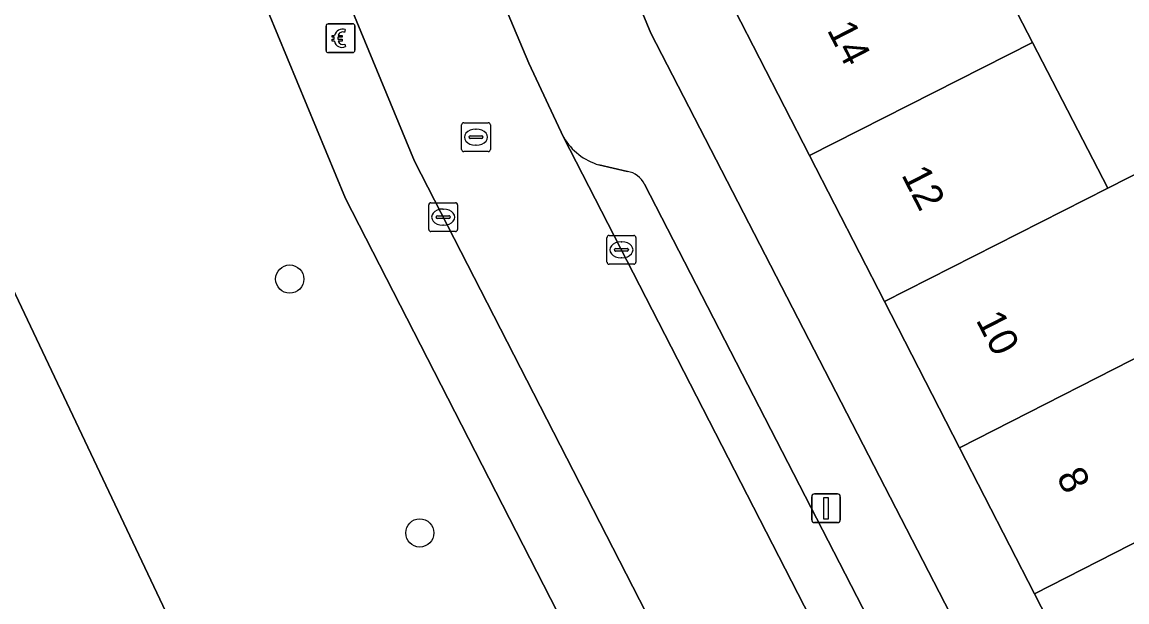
# Model space of a CAD drawing. Extents: x 160377 to 161131, y 383938 to 384853.
# Drawn here: x 161013.12 to 161051.44, y 384168.41 to 384188.53 of the extents above; entities that cross this region are included whole.
import ezdxf

# ---------------------------------------------------------------- set-up
doc = ezdxf.new("R2010")
doc.units = 0
for name, color, linetype in [('IMGEO_Betaalautomaat', 7, 'Continuous'), ('IMGEO_Boom', 7, 'Continuous'), ('IMGEO_Erf', 7, 'Continuous'), ('IMGEO_Groenvoorziening', 7, 'Continuous'), ('IMGEO_Kolk', 7, 'Continuous'), ('IMGEO_Lichtmast', 7, 'Continuous'), ('IMGEO_Pand', 7, 'Continuous'), ('IMGEO_Pand_nummerreeks', 7, 'Continuous'), ('IMGEO_Parkeervlak_open', 7, 'Continuous'), ('IMGEO_Rijbaan_lokaal_open', 7, 'Continuous'), ('IMGEO_Rioolput', 7, 'Continuous'), ('IMGEO_Voetpad_open', 7, 'Continuous')]:
    doc.layers.add(name, color=color, linetype=linetype)

msp = doc.modelspace()

# ---------------------------------------------------------------- linework, layer by layer
at = {"layer": 'IMGEO_Betaalautomaat'}
for p, q in [((161023.661, 384187.549), (161023.661, 384188.39)), ((161023.661, 384188.39), (161023.661, 384187.549)), ((161023.736, 384188.473), (161024.577, 384188.473)), ((161024.577, 384188.473), (161023.736, 384188.473)), ((161024.66, 384188.399), (161024.66, 384187.558)), ((161024.66, 384187.558), (161024.66, 384188.399)), ((161023.944, 384187.937), (161023.944, 384188.005)), ((161024.065, 384188.005), (161024.065, 384187.937)), ((161024.323, 384188.278), (161024.306, 384188.178)), ((161024.31, 384187.772), (161024.332, 384187.685)), ((161024.586, 384187.474), (161023.745, 384187.474)), ((161023.745, 384187.474), (161024.586, 384187.474))]:
    msp.add_line(p, q, dxfattribs=at)
for points in [[(161023.944, 384188.005), (161023.875, 384188.005), (161023.875, 384188.074), (161023.954, 384188.074)], [(161024.076, 384188.074), (161024.223, 384188.074), (161024.223, 384188.005), (161024.065, 384188.005)], [(161023.949, 384187.868), (161023.875, 384187.868), (161023.875, 384187.937), (161023.944, 384187.937)], [(161024.065, 384187.937), (161024.223, 384187.937), (161024.223, 384187.868), (161024.079, 384187.868)]]:
    msp.add_lwpolyline(points, dxfattribs=at)
for centre, radius, start, end in [((161023.739, 384188.396), 0.0779, 92.4484, 184.2845), ((161023.739, 384188.396), 0.0779, 92.4484, 184.2845), ((161024.583, 384188.396), 0.0779, 2.4484, 94.2845), ((161024.583, 384188.396), 0.0779, 2.4484, 94.2845), ((161024.237, 384187.998), 0.293, 73.014, 165.0139), ((161024.243, 384188.011), 0.179, 69.3236, 159.5683), ((161024.21, 384187.923), 0.267, 191.8096, 297.0389), ((161024.243, 384187.938), 0.179, 202.7625, 291.8693), ((161023.739, 384187.552), 0.0779, 182.4484, 274.2845), ((161023.739, 384187.552), 0.0779, 182.4484, 274.2845), ((161024.583, 384187.552), 0.0779, 272.4484, 4.2845), ((161024.583, 384187.552), 0.0779, 272.4484, 4.2845)]:
    msp.add_arc(centre, radius, start, end, dxfattribs=at)
at = {"layer": 'IMGEO_Boom'}
for centre in [(161022.4, 384179.616), (161026.913, 384170.805)]:
    msp.add_circle(centre, 0.489, dxfattribs=at)
at = {"layer": 'IMGEO_Erf'}
for points in [[(161027.847, 384235.775), (161032.783, 384223.835), (161034.958, 384218.572), (161037.135, 384213.306), (161039.745, 384214.388), (161041.92, 384209.128), (161044.101, 384203.852), (161046.188, 384198.804), (161043.598, 384197.672), (161045.71, 384192.581), (161048.165, 384187.827), (161050.776, 384182.773), (161053.527, 384184.17)], [(161050.73, 384163.819), (161048.231, 384168.689), (161045.627, 384173.765), (161043.025, 384178.835), (161040.426, 384183.902), (161037.824, 384188.973), (161035.658, 384194.201), (161033.482, 384199.465), (161031.304, 384204.732), (161029.129, 384209.995), (161026.959, 384215.243), (161024.801, 384220.463), (161022.879, 384219.642), (161021.24, 384223.614), (161020.418, 384223.235), (161034.926, 384188.154), (161057.391, 384144.576)]]:
    msp.add_lwpolyline(points, dxfattribs=at)
at = {"layer": 'IMGEO_Groenvoorziening'}
for points in [[(161024.34, 384182.407), (161021.323, 384189.711), (161011.935, 384212.434), (161011.739, 384212.907), (161011.64, 384213.064), (161011.528, 384213.211), (161011.402, 384213.348), (161011.265, 384213.472), (161011.118, 384213.585), (161010.961, 384213.683), (161010.796, 384213.767), (161010.624, 384213.836), (161010.446, 384213.889), (161010.265, 384213.927), (161010.081, 384213.948), (161009.895, 384213.952), (161009.71, 384213.94), (161009.527, 384213.911), (161009.347, 384213.866), (161009.172, 384213.806), (161009.003, 384213.729), (161008.989, 384213.722), (161000, 384208.958), (160981.618, 384199.217)], [(160990.804, 384145.659), (160994.784, 384139.197), (160994.905, 384139.173), (160998.463, 384138.478), (161007.166, 384134.542), (161007.773, 384134.636), (161029.797, 384138.079), (161029.845, 384138.087), (161029.42, 384139.864), (161026.658, 384162.899), (161031.19, 384164.897), (161032.918, 384165.659), (161032.625, 384166.23), (161024.34, 384182.407)]]:
    msp.add_lwpolyline(points, dxfattribs=at)
for points in [[(160994.141, 384181.268), (161013.455, 384140.491), (161027.915, 384147.34), (161008.602, 384188.117)], [(160994.141, 384181.268), (161008.602, 384188.117), (161027.915, 384147.34), (161013.455, 384140.491)]]:
    msp.add_lwpolyline(points, close=True, dxfattribs=at)
at = {"layer": 'IMGEO_Kolk'}
for p, q in [((161027.298, 384182.266), (161028.15, 384182.266)), ((161027.223, 384181.34), (161027.223, 384182.192)), ((161027.711, 384182.046), (161027.736, 384182.046)), ((161028.224, 384182.192), (161028.224, 384181.34)), ((161027.482, 384181.76), (161027.482, 384181.772)), ((161027.92, 384181.723), (161027.522, 384181.723)), ((161027.525, 384181.809), (161027.923, 384181.809)), ((161027.734, 384181.486), (161027.709, 384181.486)), ((161027.966, 384181.772), (161027.966, 384181.76)), ((161028.15, 384181.266), (161027.298, 384181.266)), ((161033.48, 384181.131), (161034.332, 384181.131)), ((161033.405, 384180.205), (161033.405, 384181.057)), ((161033.893, 384180.911), (161033.918, 384180.911)), ((161034.406, 384181.057), (161034.406, 384180.205)), ((161033.664, 384180.625), (161033.664, 384180.637)), ((161034.102, 384180.588), (161033.704, 384180.588)), ((161033.707, 384180.674), (161034.105, 384180.674)), ((161033.916, 384180.351), (161033.891, 384180.351)), ((161034.148, 384180.637), (161034.148, 384180.625)), ((161034.332, 384180.131), (161033.48, 384180.131))]:
    msp.add_line(p, q, dxfattribs=at)
for points in [[(161027.298, 384182.266), (161028.15, 384182.266)], [(161027.223, 384181.34), (161027.223, 384182.192)], [(161028.224, 384182.192), (161028.224, 384181.34)], [(161028.15, 384181.266), (161027.298, 384181.266)], [(161033.48, 384181.131), (161034.332, 384181.131)], [(161033.405, 384180.205), (161033.405, 384181.057)], [(161034.406, 384181.057), (161034.406, 384180.205)], [(161034.332, 384180.131), (161033.48, 384180.131)]]:
    msp.add_lwpolyline(points, dxfattribs=at)
for centre, radius, start, end in [((161027.3, 384182.19), 0.0765, 91.552, 178.448), ((161027.3, 384182.19), 0.0765, 91.552, 178.448), ((161028.148, 384182.19), 0.0765, 1.552, 88.448), ((161028.148, 384182.19), 0.0765, 1.552, 88.448), ((161027.522, 384181.769), 0.0403, 85.8775, 175.7526), ((161027.519, 384181.759), 0.0366, 178.938, 274.7102), ((161027.923, 384181.766), 0.043, 264.8664, 352.4533), ((161027.927, 384181.771), 0.0386, 1.7309, 96.639), ((161027.3, 384181.342), 0.0765, 181.552, 268.448), ((161027.3, 384181.342), 0.0765, 181.552, 268.448), ((161028.148, 384181.342), 0.0765, 271.552, 358.448), ((161028.148, 384181.342), 0.0765, 271.552, 358.448), ((161033.482, 384181.055), 0.0765, 91.552, 178.448), ((161033.482, 384181.055), 0.0765, 91.552, 178.448), ((161034.33, 384181.055), 0.0765, 1.552, 88.448), ((161034.33, 384181.055), 0.0765, 1.552, 88.448), ((161033.704, 384180.634), 0.0403, 85.8775, 175.7526), ((161033.701, 384180.624), 0.0366, 178.938, 274.7102), ((161034.105, 384180.631), 0.043, 264.8664, 352.4533), ((161034.109, 384180.636), 0.0386, 1.7309, 96.639), ((161033.482, 384180.207), 0.0765, 181.552, 268.448), ((161033.482, 384180.207), 0.0765, 181.552, 268.448), ((161034.33, 384180.207), 0.0765, 271.552, 358.448), ((161034.33, 384180.207), 0.0765, 271.552, 358.448)]:
    msp.add_arc(centre, radius, start, end, dxfattribs=at)
for centre, major_axis, ratio, start_param, end_param in [((161027.71, 384181.766), (-0.387, 0.002), 0.722429, 4.712389, 7.853982), ((161027.735, 384181.766), (-0.39, 0.002), 0.717154, 1.570796, 4.712389), ((161033.892, 384180.631), (-0.387, 0.002), 0.722429, 4.712389, 7.853982), ((161033.917, 384180.631), (-0.39, 0.002), 0.717154, 1.570796, 4.712389)]:
    msp.add_ellipse(centre, major_axis=major_axis, ratio=ratio, start_param=start_param, end_param=end_param, dxfattribs=at)
at = {"layer": 'IMGEO_Lichtmast'}
for p, q in [((161040.507, 384171.264), (161040.507, 384172.064)), ((161040.507, 384172.064), (161040.507, 384171.264)), ((161040.607, 384172.164), (161041.397, 384172.164)), ((161041.397, 384172.164), (161040.607, 384172.164)), ((161041.497, 384172.064), (161041.497, 384171.264)), ((161041.497, 384171.264), (161041.497, 384172.064)), ((161041.397, 384171.164), (161040.607, 384171.164)), ((161040.607, 384171.164), (161041.397, 384171.164))]:
    msp.add_line(p, q, dxfattribs=at)
msp.add_lwpolyline([(161040.927, 384172.039), (161041.077, 384172.039), (161041.077, 384171.289), (161040.927, 384171.289), (161040.927, 384172.039)], dxfattribs=at)
for centre, start, end in [((161040.607, 384172.064), 90, 180), ((161040.607, 384172.064), 90, 180), ((161041.397, 384172.064), 0, 90), ((161041.397, 384172.064), 360, 90), ((161040.607, 384171.264), 180, 270), ((161040.607, 384171.264), 180, 270), ((161041.397, 384171.264), 270, 0), ((161041.397, 384171.264), 270, 0)]:
    msp.add_arc(centre, 0.1, start, end, dxfattribs=at)
at = {"layer": 'IMGEO_Pand'}
for points in [[(161040.426, 384183.902), (161048.165, 384187.827), (161045.71, 384192.581), (161037.824, 384188.973)], [(161050.776, 384182.773), (161048.165, 384187.827), (161040.426, 384183.902), (161043.025, 384178.835)], [(161056.13, 384179.129), (161053.527, 384184.17), (161050.776, 384182.773), (161043.025, 384178.835), (161045.627, 384173.765), (161053.386, 384177.72)], [(161053.386, 384177.72), (161045.627, 384173.765), (161048.231, 384168.689), (161056.001, 384172.656), (161058.741, 384174.073), (161056.13, 384179.129)], [(161058.618, 384167.589), (161056.001, 384172.656), (161048.231, 384168.689), (161050.73, 384163.819), (161050.835, 384163.615), (161057.281, 384166.906)]]:
    msp.add_lwpolyline(points, close=True, dxfattribs=at)
at = {"layer": 'IMGEO_Parkeervlak_open'}
for points in [[(161031.902, 384184.537), (161049.465, 384150.301)], [(161034.112, 384183.352), (161033.127, 384183.578)], [(161049.824, 384153.527), (161034.709, 384182.908)]]:
    msp.add_lwpolyline(points, dxfattribs=at)
for centre, radius, start, end in [((161033.716, 384185.592), 2.098, 210.1801, 253.7082), ((161033.965, 384182.531), 0.835, 26.8891, 79.8332)]:
    msp.add_arc(centre, radius, start, end, dxfattribs=at)
at = {"layer": 'IMGEO_Rijbaan_lokaal_open'}
msp.add_lwpolyline([(161051.555, 384146.247), (161049.465, 384150.301), (161031.902, 384184.537), (161030.69, 384187.11), (161029.845, 384189.107), (161007.611, 384243.106), (161007.188, 384244.204), (161002.501, 384242.268), (161026.728, 384183.712), (161038.886, 384159.984), (161047.13, 384143.894), (161051.334, 384135.69), (161059.366, 384139.765), (161059.823, 384139.987), (161057.391, 384144.576)], dxfattribs=at)
at = {"layer": 'IMGEO_Rioolput'}
for p, q in [((161028.36, 384184.115), (161028.36, 384184.967)), ((161028.435, 384185.041), (161029.287, 384185.041)), ((161029.361, 384184.967), (161029.361, 384184.115)), ((161028.662, 384184.584), (161029.06, 384184.584)), ((161028.848, 384184.821), (161028.873, 384184.821)), ((161028.619, 384184.535), (161028.619, 384184.547)), ((161029.057, 384184.498), (161028.659, 384184.498)), ((161028.871, 384184.261), (161028.846, 384184.261)), ((161029.103, 384184.547), (161029.103, 384184.535)), ((161029.287, 384184.041), (161028.435, 384184.041))]:
    msp.add_line(p, q, dxfattribs=at)
for points in [[(161028.36, 384184.115), (161028.36, 384184.967)], [(161028.435, 384185.041), (161029.287, 384185.041)], [(161029.361, 384184.967), (161029.361, 384184.115)], [(161029.287, 384184.041), (161028.435, 384184.041)]]:
    msp.add_lwpolyline(points, dxfattribs=at)
for centre, radius, start, end in [((161028.437, 384184.965), 0.0765, 91.552, 178.448), ((161028.437, 384184.965), 0.0765, 91.552, 178.448), ((161029.285, 384184.965), 0.0765, 1.552, 88.448), ((161029.285, 384184.965), 0.0765, 1.552, 88.448), ((161028.659, 384184.544), 0.0403, 85.8775, 175.7526), ((161029.064, 384184.546), 0.0386, 1.7309, 96.639), ((161028.656, 384184.534), 0.0366, 178.938, 274.7102), ((161029.06, 384184.541), 0.043, 264.8664, 352.4533), ((161028.437, 384184.117), 0.0765, 181.552, 268.448), ((161028.437, 384184.117), 0.0765, 181.552, 268.448), ((161029.285, 384184.117), 0.0765, 271.552, 358.448), ((161029.285, 384184.117), 0.0765, 271.552, 358.448)]:
    msp.add_arc(centre, radius, start, end, dxfattribs=at)
for centre, major_axis, ratio, start_param, end_param in [((161028.847, 384184.541), (-0.387, 0.002), 0.722429, 4.712389, 7.853982), ((161028.872, 384184.541), (-0.39, 0.002), 0.717154, 1.570796, 4.712389)]:
    msp.add_ellipse(centre, major_axis=major_axis, ratio=ratio, start_param=start_param, end_param=end_param, dxfattribs=at)
at = {"layer": 'IMGEO_Voetpad_open'}
for points in [[(161051.334, 384135.69), (161047.13, 384143.894), (161046.665, 384143.657), (161038.436, 384159.755), (161038.886, 384159.984), (161026.728, 384183.712), (161002.501, 384242.268)], [(161057.391, 384144.576), (161034.926, 384188.154), (161020.418, 384223.235), (161016.957, 384231.647), (161012.644, 384242.124)], [(161000.949, 384238.997), (161008.117, 384221.66), (161009.493, 384218.333), (161009.505, 384218.303), (161011.739, 384212.907), (161011.935, 384212.434), (161021.323, 384189.711), (161024.34, 384182.407), (161032.625, 384166.23), (161032.918, 384165.659), (161036.448, 384158.766), (161044.85, 384142.402), (161046.716, 384138.743), (161047.633, 384136.971), (161047.664, 384136.926), (161050.415, 384131.358), (161051.315, 384131.821), (161056.35, 384134.403), (161060.825, 384136.697), (161060.16, 384138.173), (161053.854, 384135.006)], [(161029.845, 384189.107), (161030.69, 384187.11), (161031.902, 384184.537)], [(161033.127, 384183.578), (161034.112, 384183.352)], [(161034.709, 384182.908), (161049.824, 384153.527)]]:
    msp.add_lwpolyline(points, dxfattribs=at)
for centre, radius, start, end in [((161033.716, 384185.592), 2.098, 210.1801, 253.7082), ((161033.965, 384182.531), 0.835, 26.8891, 79.8332)]:
    msp.add_arc(centre, radius, start, end, dxfattribs=at)

# ---------------------------------------------------------------- texts
at = {"layer": 'IMGEO_Pand_nummerreeks'}
for s, rotation, p in [('14', 297.1621, (161041.021, 384188.262)), ('12', 297.1621, (161043.601, 384183.234)), ('10', 297.1637, (161046.185, 384178.198)), ('8', 297.1621, (161048.976, 384172.757))]:
    msp.add_text(s, height=1, rotation=rotation, dxfattribs=at).set_placement(p)

doc.saveas('drawing.dxf')
